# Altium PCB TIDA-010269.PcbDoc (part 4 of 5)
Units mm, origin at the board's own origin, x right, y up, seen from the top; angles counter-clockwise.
Board outline 87.61 x 53.51 mm, 8 copper layers (Top Layer, GND1, Signal 1, Power 1, Power 2, Signal 2, Layer 1, Bottom Layer), stack 1.645 mm thick; 482 components, 227 nets, 1562 pads, 953 vias.
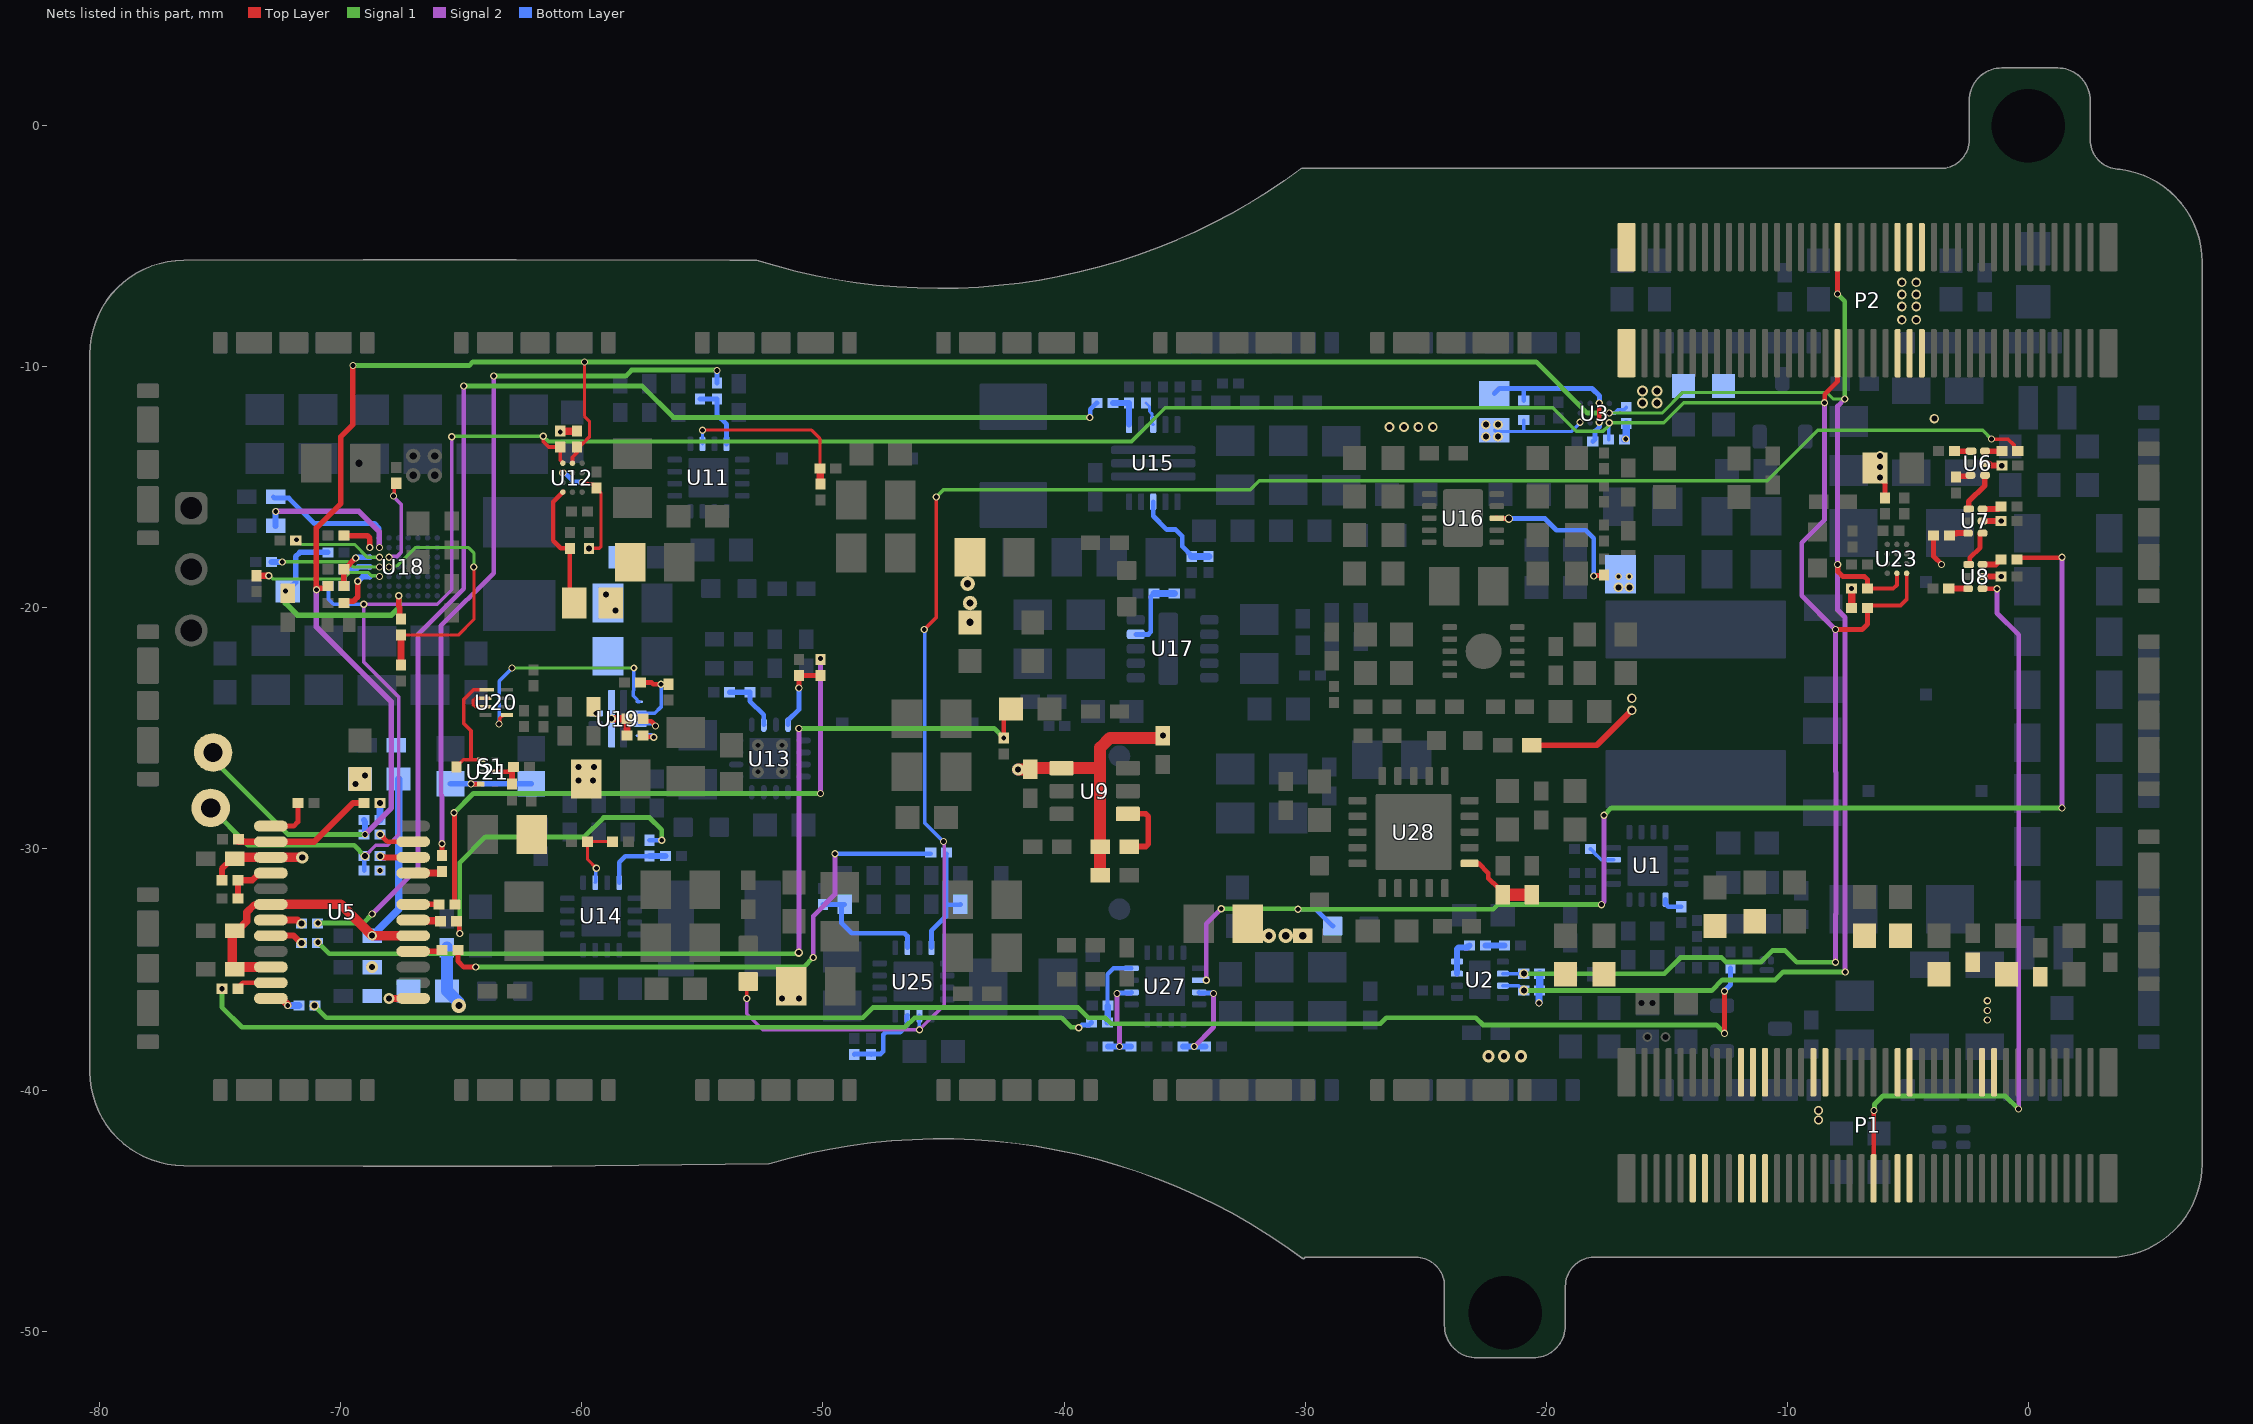
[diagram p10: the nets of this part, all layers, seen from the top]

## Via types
v1: diameter 0.6, hole 0.3, Top Layer to Bottom Layer, tented both sides, 264 vias
v2: diameter 0.4, hole 0.25, Top Layer to Bottom Layer, tented both sides, 251 vias
v3: diameter 0.3, hole 0.2, Top Layer to Bottom Layer, tented both sides, 153 vias
v4: diameter 0.3, hole 0.2, Top Layer to Bottom Layer, 95 vias
v5: diameter 0.5, hole 0.25, Top Layer to Bottom Layer, tented both sides, 67 vias
v6: diameter 0.5, hole 0.2, Top Layer to Bottom Layer, 44 vias
v7: diameter 0.35, hole 0.22, Top Layer to Bottom Layer, tented both sides, 34 vias
v8: diameter 0.45, hole 0.3, Top Layer to Bottom Layer, tented both sides, 8 vias
v9: diameter 0.3, hole 0.15, Top Layer to Bottom Layer, tented both sides, 8 vias
v10: diameter 0.5, hole 0.3, Top Layer to Bottom Layer, tented both sides, 7 vias
v11: diameter 0.35, hole 0.25, Top Layer to Bottom Layer, tented both sides, 5 vias
v12: diameter 0.38, hole 0.25, Top Layer to Bottom Layer, tented both sides, 3 vias
v13: diameter 0.4, hole 0.22, Top Layer to Bottom Layer, tented both sides, 3 vias
v14: diameter 0.4, hole 0.25, Top Layer to Bottom Layer, 3 vias
v15: diameter 0.35, hole 0.2, Top Layer to Bottom Layer, tented both sides, 2 vias
v16: diameter 0.7, hole 0.5, Top Layer to Bottom Layer, tented both sides, 1 vias
v17: diameter 0.32, hole 0.21, Top Layer to Bottom Layer, tented both sides, 1 vias
v18: diameter 0.6, hole 0.3, Top Layer to Bottom Layer, 1 vias
v19: diameter 0.45, hole 0.25, Top Layer to Bottom Layer, tented both sides, 1 vias
v20: diameter 0.36, hole 0.25, Top Layer to Bottom Layer, tented both sides, 1 vias
v21: diameter 0.5, hole 0.25, Top Layer to Bottom Layer, 1 vias

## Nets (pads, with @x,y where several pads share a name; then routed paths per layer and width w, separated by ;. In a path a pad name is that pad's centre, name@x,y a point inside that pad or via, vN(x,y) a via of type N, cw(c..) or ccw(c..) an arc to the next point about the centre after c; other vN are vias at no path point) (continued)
NetR16_2: R16.2 R138.2 U18.H5 | length 2
  Top Layer w0.23: R16.2@-69.87,-19.1 R138.2@-69.87,-18.4 -69.85,-18.4 v4(-69.383,-17.933)
  Bottom Layer w0.23: v4(-69.383,-17.933) -69.37,-17.9 U18.H5@-68.8,-17.9
NetR17_2: R17.2 U1.11 | length 1.2
  Bottom Layer w0.152: R17.2@-18.17,-30 -18.15,-30 -18.016,-30.134 -18.016,-30.154 -17.72,-30.45 U1.11@-17.2,-30.45
NetR18_2: R18.2 U1.5 | length 0.9
  Bottom Layer w0.2: U1.5@-15.05,-32.1 -15.05,-32.28 -14.93,-32.4 R18.2@-14.4,-32.4
NetR24_1: R24.1 U2.7 U2.8 | length 1.7
  Bottom Layer w0.152: R24.1@-23.292,-34 R24.1@-23.18,-34
  Bottom Layer w0.254: U2.7@-23.7,-35.175 U2.8@-23.7,-34.675 -23.7,-34.15 -23.633,-34.083 -23.263,-34.083 R24.1@-23.18,-34
NetR24_2: R24.2 R25.2 | length 0.8
  Bottom Layer w0.254: R24.2@-22.52,-34 R25.2@-21.73,-34
NetR37_1: R37.1 U5.1 | length 2
  Top Layer w0.2: U5.1@-72.9,-29.05 -71.95,-29.05 -71.78,-28.88 R37.1@-71.78,-28.1
NetR40_1: R40.1 R48.1 U5.2 | length 5.9
  Top Layer w0.254: R48.1@-74.24,-29.7 U5.2@-72.9,-29.7 -71.1,-29.7 -69.5,-28.1 R40.1@-69.03,-28.1
NetR41_1: R41.1 R49.1 U5.4 | length 2.2
  Top Layer w0.254: R49.1@-74.27,-32.05 R41.1@-74.27,-31.3 -73.675,-31.3 -73.375,-31 U5.4@-72.9,-31
NetR42_2: R42.2 U6.1 | length 0.7
  Top Layer w0.24: R42.2@-3.07,-13.5 U6.1@-2.375,-13.5
NetR43_2: R43.2 U6.3 | length 0.6
  Top Layer w0.22: R43.2@-3,-14.57 -2.965,-14.535 -2.435,-14.535 U6.3@-2.4,-14.5
NetR44_1: R44.1 U5.22 | length 1.4
  Top Layer w0.25: v7(-68.37,-30.3) -68.3,-30.3 -68.25,-30.35 U5.22@-67,-30.35
NetR45_1: R45.1 U5.23 | length 1.5
  Top Layer w0.2: v7(-68.37,-29.4) -68.07,-29.7 U5.23@-67,-29.7
NetR46_2: R46.2 U6.6 | length 0.7
  Top Layer w0.24: U6.6@-1.8,-13.5 R46.2@-1.1,-13.5
NetR47_2: R47.2 U5.12 | length 1.3
  Top Layer w0.3: U5.12@-72.9,-36.2 -72.463,-36.2 -72.2,-36.463 v4(-72.2,-36.5)
  Bottom Layer w0.3: v4(-72.2,-36.5) R47.2@-71.73,-36.5
NetR50_2: R50.2 U5.11 | length 1.5
  Top Layer w0.2: R50.2@-74.27,-35.8 -74.27,-35.75 -74.07,-35.55 U5.11@-72.9,-35.55
NetR51_2: R51.2 U7.3 | length 0.8
  Top Layer w0.24: R51.2@-3.27,-17 -3.18,-16.91 -2.98,-16.91 -2.97,-16.9 U7.3@-2.5,-16.9
NetR53_2: R53.2 U5.16 | length 1.2
  Top Layer w0.13: R53.2@-65.85,-34.25 R53.2@-65.8,-34.2
  Top Layer w0.23: U5.16@-67,-34.25 R53.2@-65.85,-34.25
NetR54_2: R54.2 U7.6 | length 0.8
  Top Layer w0.24: U7.6@-1.9,-15.9 -1.25,-15.9 -1.15,-15.8 R54.2@-1.13,-15.8
NetR55_2: R55.2 U5.8 | length 1.4
  Top Layer w0.25: U5.8@-72.9,-33.6 -71.955,-33.6 -71.655,-33.9 v2(-71.63,-33.9)
NetR56_2: R56.2 U5.7 | length 1.3
  Top Layer w0.3: U5.7@-72.9,-32.95 -71.807,-32.95 -71.657,-33.1 v2(-71.63,-33.1)
NetR57_2: R57.2 U5.18 | length 1.2
  Top Layer w0.25: U5.18@-67,-32.95 U5.18@-66.975,-32.975 ; R57.2@-65.885,-32.975 R57.2@-65.86,-33
  Top Layer w0.3: U5.18@-66.975,-32.975 R57.2@-65.885,-32.975
NetR58_2: R58.2 U5.19 | length 1.1
  Top Layer w0.23: U5.19@-67,-32.3 R58.2@-65.93,-32.3
NetR59_2: R59.2 U5.21 | length 1.2
  Top Layer w0.3: U5.21@-67,-31 R59.2@-65.8,-31
NetR60_2: R60.2 U8.3 | length 0.8
  Top Layer w0.24: R60.2@-3.3,-19.2 U8.3@-2.5,-19.2
NetR61_2: R61.2 U8.6 | length 0.9
  Top Layer w0.24: U8.6@-1.9,-18.2 -1.35,-18.2 -1.15,-18 R61.2@-1.13,-18
NetR63_1: R63.1 U9.4 | length 2.9
  Top Layer w0.23: U9.4@-37.35,-28.55 -36.611,-28.55 -36.5,-28.661 -36.5,-29.789 -36.611,-29.9 R63.1@-37.3,-29.9
NetR68_1: R68.1 R74.2 U11.6 | length 7.5
  Top Layer w0.13: v4(-55,-12.63) -50.47,-12.63 -50.13,-12.97 R68.1@-50.13,-14.225
  Top Layer w0.3: R68.1@-50.13,-14.225 -50.115,-14.24 -50.115,-14.855 R74.2@-50.1,-14.87
  Bottom Layer w0.13: U11.6@-55,-13.2 v4(-55,-12.63)
NetR75_1: R75.1 R189.1 U11.8 | length 2.7
  Bottom Layer w0.2: R75.1@-55.1,-11.33 R189.1@-54.4,-11.33 -54.4,-11.992 -54,-12.392 U11.8@-54,-13.2
NetR83_1: R83.1 R85.2 U14.6 | length 2.9
  Top Layer w0.127: v4(-59.4,-30.8) -59.77,-30.43 R85.2@-59.77,-29.7 R83.1@-58.73,-29.7
  Bottom Layer w0.127: U14.6@-59.45,-31.4 -59.425,-31.375 -59.425,-30.825 v4(-59.4,-30.8)
NetR84_1: R84.1 R87.2 U13.6 | length 2.4
  Bottom Layer w0.2: R84.1@-53.03,-23.5 -53.03,-23.87 -52.458,-24.442 -52.458,-24.842 U13.6@-52.45,-24.85
  Bottom Layer w0.22: R87.2@-53.87,-23.5 R84.1@-53.03,-23.5
NetR86_1: R86.1 R191.1 U14.8 | length 2.9
  Bottom Layer w0.2: U14.8@-58.45,-31.4 -58.45,-30.55 -58.2,-30.3 R191.1@-57.2,-30.3
  Bottom Layer w0.254: R191.1@-57.2,-30.3 R86.1@-56.53,-30.3
NetR88_1: R88.1 R190.1 U13.8 | length 3.1
  Top Layer w0.2: v4(-51,-23.33) R88.1@-51,-22.8 R190.1@-50.1,-22.8
  Bottom Layer w0.2: U13.8@-51.45,-24.85 -51.45,-24.67 -51,-24.22 v4(-51,-23.33)
NetR92_2: R92.2 R94.2 U15.11 | length 3.8
  Bottom Layer w0.2: U15.11@-36.3,-15.6 -36.3,-16.19 -35.735,-16.755 -35.369,-16.755 -35.099,-17.024 -35.099,-17.451 -34.7,-17.85 R94.2@-34.7,-17.87
  Bottom Layer w0.3: R94.2@-34.7,-17.87 R92.2@-34,-17.87
NetR96_2: R96.2 R192.2 U15.1 | length 1.6
  Bottom Layer w0.254: R192.2@-37.97,-11.5 R96.2@-37.3,-11.5 U15.1@-37.3,-12.4
NetR97_2: R97.2 U15.3 | length 1
  Bottom Layer w0.127: R97.2@-36.6,-11.5 -36.454,-11.647 -36.454,-11.852 -36.357,-11.948 -36.357,-12.343 U15.3@-36.3,-12.4
NetR103_2: R103.2 U16.8 | length 6.4
  Top Layer w0.2: v3(-18.025,-18.682) -18.006,-18.663 -17.633,-18.663 R103.2@-17.6,-18.63
  Top Layer w0.22: U16.8@-22.05,-16.28 -22.04,-16.29 -21.56,-16.29 v11(-21.55,-16.3)
  Bottom Layer w0.2: v11(-21.55,-16.3) -20.05,-16.3 -19.573,-16.777 -18.365,-16.777 -18.025,-17.117 v3(-18.025,-18.682)
NetR108_1: R108.1 R110.2 U17.4 | length 3.2
  Bottom Layer w0.13: R108.1@-36.4,-19.53 R108.1@-36.27,-19.4
  Bottom Layer w0.2: U17.4@-37.025,-21.1 -36.5,-21.1 -36.4,-21 R108.1@-36.4,-19.53
  Bottom Layer w0.3: R108.1@-36.27,-19.4 R110.2@-35.43,-19.4
NetR121_1: R121.1 R127.1 U19.2 | length 3.2
  Top Layer w0.2: R121.1@-57.57,-23.1 -57.1,-23.1 -57.03,-23.17 v4(-56.715,-23.17) R127.1@-56.4,-23.17
  Bottom Layer w0.15: U19.2@-57.619,-24.375 -56.975,-24.375 -56.715,-24.115 v4(-56.715,-23.17)
NetR122_2: R122.2 U19.4 | length 1.1
  Top Layer w0.2: R122.2@-57.47,-25.3 -57.42,-25.35 -57.038,-25.35 v3(-57.019,-25.369)
  Bottom Layer w0.2: U19.4@-57.619,-25.3 -57.116,-25.3 -57.046,-25.369 v3(-57.019,-25.369)
NetR123_1: R123.1 U20.1 U21.1 | length 4.9
  Top Layer w0.15: R123.1@-65.2,-26.6 -65.2,-26.58 -64.92,-26.3 -64.6,-26.3 ; U21.1@-64.175,-26.3 -64.6,-26.3 ; U20.1@-63.95,-23.4 -64.5,-23.4 -64.9,-23.8 -64.9,-24.8 -64.6,-25.1 -64.6,-26.3
NetR124_2: R124.2 R132.2 U21.5 | length 1.6
  Top Layer w0.2: U21.5@-63.6,-26.8 -63.05,-26.8 -62.85,-26.6 R132.2@-62.83,-26.6
  Top Layer w0.23: R124.2@-62.9,-27.3 -62.9,-26.67 R132.2@-62.83,-26.6
NetR125_2: R125.2 U19.3 | length 1.4
  Top Layer w0.2: R125.2@-57.47,-24.6 -57.37,-24.7 -57.127,-24.7 -56.927,-24.9 v3(-56.946,-24.9)
  Bottom Layer w0.13: U19.3@-57.619,-24.825 -57.021,-24.825 v3(-56.946,-24.9)
NetR126_1: R126.1 U18.F5 | length 3.6
  Top Layer w0.15: v3(-67.811,-15.36) -67.782,-15.331 -67.782,-14.912 R126.1@-67.7,-14.83
  Signal 2 w0.15: v4(-68,-17.9) -67.971,-17.871 -67.671,-17.871 -67.5,-17.7 -67.5,-15.7 -67.811,-15.389 v3(-67.811,-15.36)
NetR128_1: R128.1 R130.1 U18.F4 | length 11.3
  Top Layer w0.13: R128.1@-67.5,-21.13 -65.13,-21.13 -64.483,-20.483 v4(-64.483,-18.3)
  Top Layer w0.3: R130.1@-67.5,-22.4 R128.1@-67.5,-21.13
  Signal 2 w0.13: v4(-68,-18.3) v4@-67.967,-18.267
  Signal 1 w0.13: v4(-68,-18.3) -67.967,-18.267 -67.684,-18.267 -66.916,-17.5 -64.7,-17.5 -64.483,-17.717 v4(-64.483,-18.3)
NetR129_2: R129.2 U19.9
  other v4: -59.419,-24.375
NetR134_1: R134.1 U18.G7 | length 5.3
  Bottom Layer w0.2: R134.1@-72.8,-15.4 -72.753,-15.447 -72.153,-15.447 -71.1,-16.5 -68.6,-16.5 -68.406,-16.694 -68.406,-17.094 U18.G7@-68.4,-17.1
NetR135_1: R135.1 U18.G6 | length 5.9
  Signal 2 w0.23: v4(-72.7,-16) -69.25,-16 -68.4,-16.85 v4(-68.4,-17.5)
  Bottom Layer w0.25: R135.1@-72.7,-16.6 v4(-72.7,-16)
NetR139_2: R139.2 R193.2 U18.H4 | length 1.8
  Bottom Layer w0.23: R193.2@-69.87,-19.1 R139.2@-69.87,-18.4 -69.375,-18.4 -69.275,-18.3 U18.H4@-68.8,-18.3
NetR140_2: R140.2 U18.G3 | length 5.3
  Top Layer w0.254: R140.2@-73.5,-18.67 v3(-72.99,-18.67)
  Signal 2 w0.13: v3(-72.99,-18.67) v3@-72.953,-18.67 ; v4@-68.433,-18.667 v4(-68.4,-18.7)
  Signal 1 w0.13: v3@-72.953,-18.67 -72.823,-18.8 -69.9,-18.8 -69.63,-18.53 -68.87,-18.53 -68.733,-18.667 v4@-68.433,-18.667
NetR141_2: R141.2 U18.G4 | length 4.6
  Signal 1 w0.13: v4(-72.43,-18.1) -72.415,-18.085 -69.715,-18.085 -69.5,-18.3 v4(-68.4,-18.3)
  Bottom Layer w0.254: R141.2@-72.87,-18.1 v4(-72.43,-18.1)
NetR142_2: R142.2 U18.H6 | length 1.5
  Top Layer w0.23: R142.2@-69.87,-17 -68.903,-17 -68.8,-17.103 v4(-68.8,-17.5)
NetR143_2: R143.2 U18.H3 | length 1.9
  Top Layer w0.23: R143.2@-69.87,-19.8 -69.796,-19.726 -69.476,-19.726 -69.3,-19.55 v4(-69.3,-18.9)
  Bottom Layer w0.23: v4(-69.3,-18.9) -69.281,-18.9 -69.081,-18.7 U18.H3@-68.8,-18.7
NetR144_2: R144.2 U18.G5 | length 3.7
  Signal 1 w0.13: v4(-71.836,-17.173) -71.644,-17.365 -69.435,-17.365 -68.9,-17.9 v4(-68.4,-17.9)
NetR161_2: R161.2 R162.2 U25.15 | length 3.5
  Bottom Layer w0.2: R161.2@-48.7,-38.53 -48.7,-38.5 R162.2@-48,-38.5 ; R162.2@-48,-38.53 -47.97,-38.5 -47.603,-38.5 -47.5,-38.397 -47.5,-37.702 -47.397,-37.6 -46.8,-37.6 -46.641,-37.441 ; -46.6,-37.4 -46.52,-37.32 -46.52,-36.92 U25.15@-46.5,-36.9
NetR165_1: R165.1 R168.2 U25.6 | length 5.2
  Bottom Layer w0.16: R165.1@-49.225,-32.425 R165.1@-49.1,-32.3
  Bottom Layer w0.2: R168.2@-50,-32.3 R165.1@-49.1,-32.3 ; R165.1@-49.225,-32.425 -49.225,-33.075 -48.8,-33.5 -46.617,-33.5 -46.5,-33.617 U25.6@-46.5,-34.1
NetR169_1: R169.1 R186.1 U25.8 | length 4.8
  Bottom Layer w0.2: U25.8@-45.5,-34.1 -45.5,-33.4 -44.9,-32.8 -44.9,-32.315 ; R186.1@-44.87,-30.2 -44.9,-30.23 -44.9,-32.315 ; R169.1@-44.3,-32.3 -44.315,-32.315 -44.9,-32.315
NetR173_2: R173.2 R174.2 U27.15 | length 4.1
  Signal 2 w0.2: v4(-34.6,-38.2) -33.8,-37.4 v4(-33.8,-36)
  Bottom Layer w0.2: U27.15@-34.4,-35.95 -34.38,-35.97 -33.857,-35.97 v4(-33.8,-36)
  Bottom Layer w0.254: R173.2@-35.07,-38.2 v4(-34.6,-38.2) R174.2@-34.13,-38.2
NetR177_1: R177.1 R180.2 U27.6 | length 3.8
  Signal 2 w0.2: v4(-37.8,-36) -37.8,-37.212 -37.7,-37.312 v4(-37.7,-38.2)
  Bottom Layer w0.2: v4(-37.8,-36) -37.781,-35.981 -37.581,-35.981 -37.57,-35.97 -37.22,-35.97 U27.6@-37.2,-35.95
  Bottom Layer w0.254: R177.1@-38.17,-38.2 v4(-37.7,-38.2) R180.2@-37.23,-38.2
NetR179_1: R179.1 R182.2 U28.16 | length 3.3
  Top Layer w0.2: U28.16@-23.175,-30.6 -22.8,-30.6 -22.4,-31 -22.4,-31.224 -22.224,-31.4 -22.2,-31.4 -21.8,-31.8 R179.1@-21.8,-31.9
  Top Layer w0.5: R179.1@-21.8,-31.9 R182.2@-20.6,-31.9
NetR181_1: R181.1 R187.1 U27.8 | length 3.1
  Bottom Layer w0.18: R181.1@-38.17,-36.5 -38.185,-36.515 -38.2,-36.5 -38.2,-35.2 -37.95,-34.95 U27.8@-37.2,-34.95
  Bottom Layer w0.254: R187.1@-38.2,-37.2 -38.185,-37.185 R181.1@-38.185,-36.515
NetS1_2: S1.2 S1.4 U21.3 | length 3.7
  Top Layer w0.2: v4(-64.6,-27.3) U21.3@-64.2,-27.3
  Bottom Layer w0.23: S1.4@-65.45,-27.3 v4(-64.6,-27.3) S1.2@-62.1,-27.3
NetU6_4: U6.4 U7.1 | length 1.7
  Top Layer w0.23: U7.1@-2.475,-15.9 -2.475,-15.593 -1.8,-14.917 U6.4@-1.8,-14.5
NetU7_4: U7.4 U8.1 | length 1.6
  Top Layer w0.2: U8.1@-2.475,-18.2 -2.428,-18.153 -2.428,-17.928 -2,-17.5 -2,-16.95 -1.95,-16.9 U7.4@-1.9,-16.9
NetU19_1: U19.1 U20.5 | length 9.8
  Top Layer w0.14: v4(-63.435,-24.818) -63.404,-24.787 -63.404,-24.584 -63.27,-24.45 U20.5@-63.1,-24.45
  Signal 1 w0.14: v3(-62.895,-22.495) v9(-57.842,-22.495)
  Bottom Layer w0.14: v4(-63.435,-24.818) -63.435,-23.035 v3(-62.895,-22.495) ; v9(-57.842,-22.495) -57.842,-23.421 -57.87,-23.45 -57.87,-23.649 -57.699,-23.82 -57.699,-23.88 -57.679,-23.9 U19.1@-57.619,-23.9
NetU20_2: U20.2 U20.3 | length 1.2
  Top Layer w0.14: U20.3@-64,-24.1 -64.412,-24.1 -64.5,-24.012 -64.5,-23.838 -64.412,-23.75 U20.2@-64,-23.75
PHV: C13.1 L4.2 P2.79 P2.80
  other v8: -16,-11.5 -15.4,-11.5 -16,-11 -15.4,-11
"Power Good": P1.39 U8.4 | length 32
  Top Layer w0.2: P1.39@-6.421,-43.664 -6.41,-43.654 -6.41,-40.86 v3(-6.4,-40.85) ; U8.4@-1.9,-19.2 -1.895,-19.205 -1.305,-19.205 v3(-1.3,-19.21)
  Signal 2 w0.2: v3(-1.3,-19.21) -1.3,-20.217 -0.4,-21.117 v3@-0.4,-40.793
  Signal 1 w0.2: v3(-6.4,-40.85) -6.381,-40.831 -6.381,-40.599 -6.031,-40.249 -0.949,-40.249 v3(-0.406,-40.793)
RX_PG_1V2: D14.2 R61.1 U27.14 | length 56
  Top Layer w0.2: R61.1@-0.47,-18 -0.389,-17.919 1.381,-17.919 v4(1.4,-17.9)
  Signal 2 w0.2: v4(-34.1,-35.45) -34.1,-33.101 v3(-33.481,-32.482) ; v3(-17.704,-32.311) -17.704,-32.284 -17.6,-32.18 v3(-17.6,-28.6) ; v3(1.4,-28.3) v4(1.4,-17.9)
  Signal 1 w0.2: v3(-33.481,-32.482) v3@-30.3,-32.482 ; v3(-30.3,-32.5) -22.2,-32.5 -22.011,-32.311 v3(-17.704,-32.311) ; v3(-17.6,-28.6) -17.3,-28.3 v3(1.4,-28.3)
  Bottom Layer w0.2: v3(-30.3,-32.5) -29.55,-32.5 D14.2@-28.85,-33.2
RX_PG_1V8: D7.2 R46.1 U25.14 | length 78.9
  Top Layer w0.15: v4(-53.163,-36.2) -53.163,-35.563 D7.2@-53.1,-35.5 ; v3(-45.8,-20.9) -45.3,-20.4 v3(-45.3,-15.4) ; v3(-1.525,-13) -0.842,-13 -0.595,-13.247 -0.595,-13.365 -0.46,-13.5 R46.1@-0.44,-13.5
  Signal 2 w0.15: v4(-53.163,-36.2) -53.163,-36.837 -52.5,-37.5 -52.495,-37.495 -46.005,-37.495 v4(-46,-37.5) -44.975,-36.475 -44.975,-29.715 v3(-45,-29.69)
  Signal 1 w0.15: v3(-45.3,-15.4) -45,-15.1 -32.281,-15.1 -31.906,-14.725 -10.825,-14.725 -8.734,-12.634 -1.891,-12.634 v3(-1.525,-13)
  Bottom Layer w0.15: v4(-46,-37.5) U25.14@-46,-36.9 ; v3(-45.8,-20.9) -45.775,-20.925 -45.775,-28.925 -45.01,-29.69 v3(-45,-29.69)
SCL: P2.45 R27.2 R32.1 R38.1 R44.2 R73.1 R148.1 R193.1 SCL.1 U2.2 U3.A1 U12.A1 U23.A1 | length 139
  Top Layer w0.152: v3(-61.603,-12.881) -61.6,-12.884 -61.6,-13.1 -61.37,-13.33 R73.1@-60.9,-13.33 -60.9,-13.869 -60.79,-13.979 U12.A1@-60.79,-14 ; R148.1@-6.67,-20 -6.67,-19.9 -5.3,-19.9 -5.05,-19.65 U23.A1@-5.05,-18.565
  Top Layer w0.2: v4(-8.459,-11.495) -8.445,-11.482 -8.445,-11.145 -7.921,-10.621 P2.45@-7.921,-9.438 ; v4(-8,-20.9) -6.9,-20.9 -6.67,-20.67 R148.1@-6.67,-20
  Signal 2 w0.15: v20(-69,-30.3) -68.55,-29.85 -68.05,-29.85 -67.6,-29.4 -67.6,-23.7 -69.05,-22.25 v3(-69.05,-19.85) -66,-19.85 -65.4,-19.25 v4(-65.4,-12.9)
  Signal 2 w0.2: v4(-8.459,-11.495) -8.459,-16.359 -9.4,-17.3 -9.4,-19.5 v4(-8,-20.9) ; v4@-8.033,-20.933 -8.014,-20.933 -8,-20.946 -8,-26.794 -7.975,-26.819 -7.975,-32.686 -8,-32.711 v3(-8,-34.7)
  Signal 1 w0.15: v4(-65.4,-12.9) -65.381,-12.881 v3(-61.603,-12.881) -61.384,-13.1 -37.2,-13.1 -35.8,-11.7 -19.73,-11.7 -18.755,-12.675 -17.645,-12.675 v3@-17.41,-12.44 ; v3(-17.381,-12.319) -15.119,-12.319 -14.295,-11.495 v4(-8.459,-11.495)
  Signal 1 w0.2: SCL.1@-75.4,-28.3 -73.85,-29.85 -69.45,-29.85 v20(-69,-30.3) ; v2(-20.93,-35.175) -15.098,-35.175 -14.428,-34.505 -12.716,-34.505 -12.526,-34.695 -11.1,-34.695 -10.62,-34.215 -10.085,-34.215 -9.6,-34.7 v3(-8,-34.7)
  Bottom Layer w0.15: R193.1@-70.51,-19.1 -70.51,-19.64 -70.3,-19.85 v3(-69.05,-19.85)
  Bottom Layer w0.152: U2.2@-21.8,-35.175 v2(-20.93,-35.175) ; R32.1@-17.411,-13.019 -17.411,-12.37 -17.381,-12.34 v3(-17.381,-12.319)
  Bottom Layer w0.2: R38.1@-69.03,-30.9 -69.03,-30.33 v20(-69,-30.3)
SDA: P2.46 R16.1 R26.2 R33.1 R39.1 R45.2 R72.1 R149.1 SDA.1 U2.3 U3.A2 U12.A2 U23.A2 | length 149.1
  Top Layer w0.13: R72.1@-60.2,-13.445 -60.143,-13.387 -59.69,-12.935 ; R72.1@-60.2,-13.33 -60.2,-13.31 -60.055,-13.165 -59.951,-13.165 -59.69,-12.904 -59.69,-12.253 -59.897,-12.047 v3(-59.897,-9.8)
  Top Layer w0.152: U12.A2@-60.39,-14 -60.39,-13.75 -60.2,-13.56 R72.1@-60.2,-13.445 ; R149.1@-6.67,-19.2 -5.6,-19.2 -5.45,-19.05 U23.A2@-5.45,-18.565
  Top Layer w0.2: v4(-7.921,-6.979) P2.46@-7.921,-5.038 ; v4(-7.91,-18.2) -7.891,-18.219 -7.891,-18.509 -7.7,-18.7 -6.8,-18.7 -6.67,-18.83 R149.1@-6.67,-19.2
  Top Layer w0.23: R16.1@-70.53,-19.1 -70.625,-19.195 -70.936,-19.195 -70.991,-19.25 v4(-71.01,-19.25) -71.01,-16.682 -70,-15.672 -70,-12.899 -69.5,-12.399 v3(-69.5,-9.95)
  Signal 2 w0.2: v3(-7.615,-11.333) -7.91,-11.628 v4(-7.91,-18.2) -7.91,-20.09 -7.6,-20.4 -7.6,-35.099 v3(-7.597,-35.101)
  Signal 2 w0.23: v4(-71.01,-19.25) -71.01,-20.79 -67.9,-23.9 -67.9,-28.3 v4(-69,-29.4)
  Signal 1 w0.13: v4@-69.03,-29.4 v4(-69,-29.4) ; v3(-17.381,-11.919) -15.186,-11.919 -14.331,-11.063 -8.375,-11.063 -8.105,-11.333 v3(-7.615,-11.333)
  Signal 1 w0.2: SDA.1@-75.3,-26 -75.3,-26.3 -72.2,-29.4 v4@-69.03,-29.4 ; v3(-69.5,-9.95) -64.678,-9.95 -64.528,-9.8 v3(-59.897,-9.8) -20.416,-9.8 -18.297,-11.919 v3(-17.381,-11.919) ; v2(-20.93,-35.875) -13.141,-35.875 -12.701,-35.435 -10.501,-35.435 -10.166,-35.1 -9.834,-35.1 -9.833,-35.101 v3(-7.597,-35.101) ; v4@-7.91,-6.99 v4(-7.921,-6.979) -7.615,-7.285 v3(-7.615,-11.333)
  Bottom Layer w0.152: U2.3@-21.8,-35.675 -21.15,-35.675 -20.95,-35.875 v2(-20.93,-35.875) ; v3(-17.381,-11.919) -17.158,-11.919 -17.028,-11.788 -16.781,-11.788 R33.1@-16.681,-11.689
  Bottom Layer w0.25: R39.1@-69.03,-28.8 -69,-28.9 v4(-69,-29.4)
SYNC_1V2_RX: R50.1 R187.2 | length 37.6
  Signal 1 w0.2: v13(-74.93,-35.8) -74.93,-36.57 -74.1,-37.4 -46.6,-37.4 -46.2,-37 -40.1,-37 -39.705,-37.395 -39.409,-37.395 v3(-39.39,-37.414)
  Bottom Layer w0.2: v3(-39.39,-37.414) -39.363,-37.414 -39.259,-37.31 -38.97,-37.31 R187.2@-38.86,-37.2
SYNC_1V8_FX3: R57.1 R191.2 | length 13.8
  Top Layer w0.2: R57.1@-65.2,-33 -65.197,-33 -65.087,-33.11 -65.087,-33.491 v3(-65.068,-33.51)
  Signal 1 w0.2: v3(-65.068,-33.51) -65.068,-30.568 -64,-29.5 -59.9,-29.5 -59.1,-28.7 -57.196,-28.7 -56.69,-29.206 v3(-56.69,-29.64)
  Bottom Layer w0.2: R191.2@-57.2,-29.64 v3(-56.69,-29.64)
SYNC_1V8_RX: R53.1 R186.2 | length 24.1
  Top Layer w0.2: R53.1@-65.14,-34.2 -65.14,-34.66 -64.9,-34.9 v3(-64.4,-34.9)
  Signal 2 w0.2: v3(-50.4,-34.5) -50.4,-32.786 -49.5,-31.886 v3(-49.5,-30.2)
  Signal 1 w0.2: v3(-64.4,-34.9) -50.8,-34.9 v3(-50.4,-34.5)
  Bottom Layer w0.2: v3(-49.5,-30.2) R186.2@-45.53,-30.2
SYNC_5V_TX: R56.1 R192.1 | length 53.1
  Signal 2 w0.2: v3(-68.7,-32.7) -66.8,-30.8 -66.8,-21.11 -64.9,-19.21 v3(-64.9,-10.8)
  Signal 1 w0.2: v7(-70.949,-33.076) -69.076,-33.076 v3(-68.7,-32.7) ; v3(-64.9,-10.8) -57.5,-10.8 -56.2,-12.1 v3(-38.933,-12.1)
  Bottom Layer w0.2: v3(-38.933,-12.1) -38.914,-12.081 -38.914,-11.764 -38.65,-11.5 R192.1@-38.63,-11.5
SYNC_-5V_TX: C124.2 R55.1 R111.2 | length 39.5
  Top Layer w0.2: v3(-42.5,-25.4) -42.5,-24.5 C124.2@-42.2,-24.2
  Signal 2 w0.2: v7(-51,-34.3) v3(-51,-25)
  Signal 1 w0.2: v7(-70.949,-33.876) -70.475,-34.35 -51.05,-34.35 v7(-51,-34.3) ; v3(-51,-25) -42.9,-25 v3(-42.5,-25.4)
SYNC_FPGA_1V: R58.1 R190.2 | length 24.9
  Top Layer w0.2: v3(-65.3,-28.5) -65.285,-28.515 -65.285,-32.285 R58.1@-65.27,-32.3
  Signal 2 w0.2: v3(-50.1,-27.7) v3(-50.1,-22.1)
  Signal 1 w0.2: v3(-65.3,-28.5) -64.5,-27.7 v3(-50.1,-27.7)
SYNC_FPGA_2V5: R59.1 R189.2 | length 30.7
  Top Layer w0.2: R59.1@-65.8,-30.27 v3(-65.8,-29.781)
  Signal 2 w0.2: v3(-65.8,-29.781) -65.8,-27.794 -65.85,-27.744 -65.85,-20.75 -63.656,-18.556 v3(-63.656,-10.387)
  Signal 1 w0.2: v3(-63.656,-10.387) -58.187,-10.387 -57.94,-10.14 -54.41,-10.14 v3(-54.4,-10.15)
  Bottom Layer w0.2: R189.2@-54.4,-10.67 v3(-54.4,-10.15)
SYNC_HV_TX: R12.1 R47.1 | length 62.4
  Top Layer w0.2: v3(-12.6,-37.65) v3(-12.6,-35.9)
  Signal 1 w0.2: v2(-71.1,-36.5) -70.6,-37 -48.343,-37 -47.918,-36.575 -39.425,-36.575 -39,-37 -38.3,-37 -38.05,-37.25 -26.88,-37.25 -26.63,-37 -22.922,-37 -22.622,-37.3 -12.95,-37.3 v3(-12.6,-37.65)
  Bottom Layer w0.2: v3(-12.6,-35.9) -12.6,-35.873 -12.35,-35.623 R12.1@-12.35,-34.93
USB_5V: P2.31 P2.32 P2.33 P2.34 P2.35 P2.36 R116.1 R146.2 | length 1.5
  Top Layer w0.2: R116.1@-6.36,-14.2 -6.46,-14.2 -6.46,-14.325 -5.95,-14.835 R146.2@-5.95,-15.435
  other v2: -6.15,-14.6 -6.15,-14.15 -6.15,-13.7 -3.9,-12.15 -5.25,-8.05 -4.65,-8.05 -5.25,-7.5 -4.65,-7.5 -5.25,-7 -4.65,-7 -5.25,-6.5 -4.65,-6.5
VBUS: C16.1 C34.1 C53.1 C54.1 C55.1 C61.1 C131.1 C132.1 C133.1 pad.8@-43.9,-20.6 pad.9@-43.9,-19.8 pad.10@-44,-19 R9.2 R28.1 R30.2 R51.1 R62.2 R63.2 R66.1 R70.2 R91.1 R105.1 R122.1 R125.1 R163.1 R164.2 R175.1 R176.2 U3.B1 U3.B3 U6.5 U7.5 U8.5 U9.1 U12.B1 U12.C3 U19.6 | length 33.1
  Top Layer w0.127: U12.C3@-59.99,-14.8 -59.97,-14.82 -59.763,-14.82 -59.719,-14.864 -59.547,-14.864 -59.4,-15.01 C61.1@-59.4,-15.03
  Top Layer w0.13: v2(-59.7,-17.53) -59.282,-17.53 -59.2,-17.448 -59.2,-15.25 -59.4,-15.05 C61.1@-59.4,-15.03
  Top Layer w0.2: v3(-17.8,-12.3) v3(-17.8,-11.5) ; R51.1@-3.93,-17 -3.93,-17.87 v3(-3.6,-18.2)
  Top Layer w0.24: R164.2@-20.6,-25.7 -17.9,-25.7 v2(-16.45,-24.25) ; U8.5@-1.9,-18.7 v7(-1.13,-18.7) ; U7.5@-1.9,-16.4 v7(-1.13,-16.4) ; U6.5@-1.8,-14 -1.77,-14.03 -1.597,-14.03 -1.527,-14.1 v7(-1.1,-14.1)
  Top Layer w0.3: v7(-58.769,-24.6) R125.1@-58.13,-24.6 R122.1@-58.13,-25.3 ; C16.1@-41.4,-26.7 C16.1@-41.35,-26.65 ; -38.508,-26.65 -38.5,-26.658
  Top Layer w0.5: v5(-41.9,-26.7) C16.1@-41.4,-26.7 ; C16.1@-41.35,-26.65 U9.1@-40.1,-26.65 -38.508,-26.65 ; R62.2@-38.5,-31.1 R63.2@-38.5,-29.9 -38.5,-26.658 -38.5,-25.8 -38.1,-25.4 R9.2@-35.9,-25.4
  Signal 2 w0.2: pad.8@-43.9,-20.6 pad.8@-43.872,-20.572
  Signal 2 w0.24: v7(-1.13,-16.4) v7@-1.115,-16.385 ; v7@-1.115,-14.115 v7(-1.1,-14.1)
  Bottom Layer w0.2: v4(-60.79,-14.4) -60.771,-14.419 -60.686,-14.419 -60.324,-14.781 -60.019,-14.781 v4(-60,-14.8) ; R28.1@-22.151,-11.109 -21.943,-10.9 -20.912,-10.9 ; R30.2@-20.93,-11.4 -20.93,-10.918 -20.912,-10.9 ; C34.1@-18.07,-13.1 -17.97,-13 -17.97,-12.67 -17.787,-12.487 -17.787,-12.324 U3.B1@-17.781,-12.319 ; U3.B3@-17.781,-11.519 -17.787,-11.513 -17.787,-11.213 -18.1,-10.9 -20.912,-10.9
  other v1: -31.5,-33.6 -30.8,-33.6 -30.1,-33.6
  other v2: -35.9,-25.3 -16.45,-23.75 -26.5,-12.5 -25.9,-12.5 -25.3,-12.5 -24.7,-12.5
  other v5: -51.7,-36.2 -51,-36.2 -58.6,-20.1 -59,-19.45
VBUS_HV: R2.1 R28.2 R31.2 U3.D1 | length 4.3
  Signal 2 w0.13: v3(-18.6,-12.3) v3@-18.567,-12.333
  Bottom Layer w0.127: -20.93,-12.677 R31.2@-20.93,-12.2
  Bottom Layer w0.13: R28.2@-22.151,-12.629 -22.103,-12.677 -20.93,-12.677 -18.94,-12.677 U3.D1@-18.581,-12.319
  other v2: -17,-19.15 -16.55,-19.15 -22.5,-12.9 -22,-12.9 -22.5,-12.4 -22,-12.4
  other v9: -17,-18.7 -16.55,-18.7
VCC_AUX_1V8: C50.1 C86.1 L9.1 L15.2 P1.20 P1.22 R26.1 R27.1 R32.2 R33.2 R72.2 R73.2 R148.2 R149.2 | length 6.1
  Top Layer w0.3: v3(-60.9,-12.7) -60.87,-12.67 R72.2@-60.2,-12.67 ; R148.2@-7.33,-20 v3(-7.33,-19.2)
  Bottom Layer w0.3: v3(-20.3,-36.385) -20.3,-35.905 R26.1@-20.27,-35.875 R27.1@-20.27,-35.175 ; R32.2@-16.741,-13.019 -16.681,-12.959 R33.2@-16.681,-12.349
  Bottom Layer w0.5: C50.1@-65.6,-34.1 L9.1@-65.6,-35.9 -65.575,-35.9 -65.119,-36.356 -65.119,-36.481 v1(-65.1,-36.5)
  other v3: -1.7,-37.1 -1.7,-36.7 -1.7,-36.3 -16.7,-13
VCC_INT_1V: C87.1 L13.2 P1.33 P1.34 P1.35 P1.36
VCCO_2V5: C47.1 C57.1 L8.1 L11.2 P1.48 P1.50
  other v5: -22.4,-38.6 -21.75,-38.6 -21.05,-38.6 -69.4,-27.3 -69,-26.95
  other v12: -8.7,-41.25 -8.7,-40.85
VDD: C42.1 C43.1 C51.1 L9.2 R38.2 R39.2 R40.2 R41.2 U5.3 U5.13 | length 5.7
  Top Layer w0.254: R41.2@-74.93,-31.3 -74.93,-30.83 -74.5,-30.4 C42.1@-74.4,-30.4
  Top Layer w0.3: v19(-68,-36.2) U5.13@-67,-36.2
  Top Layer w0.4: C42.1@-74.4,-30.4 -74.35,-30.35 U5.3@-72.9,-30.35 v5(-71.6,-30.35)
  Signal 2 w0.3: v5@-68.792,-34.9 v5@-68.792,-34.862
  Bottom Layer w0.3: v2@-68.4,-28.1 -68.37,-28.13 R39.2@-68.37,-28.8
  other v2: -68.37,-28.1
  other v4: -68.37,-30.9
  other v5: -68.7,-34.9
VDD_CLK_2.5V: C39.1 C40.1 C41.1 C52.1 L8.2 U5.6 U5.10 U5.17 | length 18.6
  Top Layer w0.3: C39.1@-74.5,-34.85 -74.45,-34.9 C39.1@-74.4,-34.9 ; C40.1@-74.4,-33.4 -74.3,-33.4 -73.9,-33 -73.9,-32.624 -73.604,-32.329 -72.929,-32.329 U5.6@-72.9,-32.3
  Top Layer w0.4: C39.1@-74.5,-34.85 C40.1@-74.5,-33.5 ; C39.1@-74.4,-34.9 U5.10@-72.9,-34.9 ; U5.6@-72.9,-32.3 -70,-32.3 v2(-68.7,-33.6) U5.17@-67,-33.6
  Bottom Layer w0.3: v2(-68.7,-33.6) -68.6,-33.6 -68.45,-33.45 -68.45,-33.35 -67.6,-32.5 L8.2@-67.6,-27.1
VDD_FPGA: R66.2 R67.1 R71.2 R81.1 R82.1 U12.D1 | length 5.3
  Top Layer w0.152: R66.2@-60.5,-19.62 R66.2@-60.32,-19.8
  Top Layer w0.2: U12.D1@-60.79,-15.2 -61.19,-15.6 -61.19,-17.21 -60.87,-17.53 R71.2@-60.5,-17.53 R66.2@-60.5,-19.62
  other v5: -60.132,-27.158 -59.532,-27.158 -60.141,-26.593 -59.491,-26.6
VDDM_LV5: C117.1 L18.2 P1.67 P1.69
VDDP_LV5: C107.1 L17.2 P1.57 P1.58 P1.59 P1.60 P1.61 P1.62
VREG: C144.1 R128.2 R133.2 R136.2 U18.E1 | length 10.1
  Top Layer w0.23: v4(-67.6,-19.5) -67.6,-19.941 -67.55,-19.991 -67.55,-20.42 R128.2@-67.5,-20.47
  Signal 1 w0.23: v4@-72.3,-19.319 -72.3,-19.8 -71.8,-20.3 -67.9,-20.3 -67.6,-20 v4(-67.6,-19.5)
  Bottom Layer w0.23: v4(-72.3,-19.3) -72.233,-19.3 -71.873,-18.94 -71.873,-17.873 -71.7,-17.7 R136.2@-70.55,-17.7
pads on no net: D11.1S D11.2S D12.1S D12.2S P1.1 P1.2 P1.3 P1.4 P1.5 P1.6 P1.7 P1.8 P1.11 P1.12 P1.13 P1.14 P1.15 P1.16 P1.25 P1.29 P1.30 P1.75 P1.76 P1.77 P1.78 P2.1 P2.2 P2.5 P2.6 P2.9 P2.10 P2.13 P2.14 P2.15 P2.16 P2.19 P2.20 P2.21 P2.22 P2.25 P2.26 P2.27 P2.28 P2.37 P2.38 P2.43 P2.65 P2.66 P2.67 P2.68 P2.75 P2.76 P2.77 P2.78 Q3.1@-11.05,-34.625 Q3.2@-10.65,-34.625 U1.12 U1.15 U3.A3 U3.B2 U3.C2 U5.15 U5.24 U11.17@-54.75,-14.6 U12.A3 U12.B2 U12.C2 U14.17@-59.2,-32.8 U15.6@-35.1,-13.45 U15.6@-36.3,-13.45 U15.6@-37.5,-13.45 U15.7@-35.1,-14 U15.7@-36.3,-14 U15.7@-37.5,-14 U15.8@-35.1,-14.55 U15.8@-36.3,-14.55 U15.8@-37.5,-14.55 U15.9 U17.8 U17.9 U17.10 U17.11@-35.675,-20.67 U17.11@-35.675,-21.7 U17.11@-35.675,-22.73 U23.A3 U23.B2 U23.C2 U25.17@-46.25,-35.5 U27.17@-35.8,-35.7 U28.2 U28.3 U28.4 U28.13 U28.14 U28.17
copper on no net: | length 0
  Top Layer w0.152: -76.52,-1.851 -76.516,-1.847

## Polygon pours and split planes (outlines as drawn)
GND on Bottom Layer "BOTTOM_LAYER_GND_P464" (solid, remove dead copper, pour order 464): -27.4,-20.6 -27,-20.2 -27,-18.405 -27.305,-18.1 -32.692,-18.1 -34.492,-19.9 -34.492,-20.648 -34.344,-20.796 -33.18,-20.796 -32.857,-21.119 -30.669,-21.119 -30.4,-20.85 -29.45,-20.85 -29.2,-20.6
GND on Bottom Layer "BOTTOM_LAYER_GND_P463" (solid, remove dead copper, pour order 463): -20.9,-19.905 -20.805,-20 -20,-20 -19.9,-19.9 -19.9,-16.9 -20,-16.8 -20.827,-16.8 -20.9,-16.873
GND on Bottom Layer "BOTTOM_LAYER_GND_P462" (solid, remove dead copper, pour order 462): 22 vertices, not listed, extent -80.33,-47 7.206,-1.851
HVGND on Bottom Layer "BOTTOM_LAYER_HVGND_P458" (solid, remove dead copper, pour order 458): -22.3,-32.275 -22.3,-33.225 -19.915,-33.225 -18.6,-31.91 -18.6,-29.79 -18.89,-29.5 -19.65,-29.5 -20,-29.85 -20,-31.19 -21.085,-32.275
GND on Bottom Layer "BOTTOM_LAYER_GND_P457" (solid, remove dead copper, pour order 457): -22.9,-32.275 -25.325,-32.275 -25.5,-32.45 -25.5,-34 -25.3,-34.2 -24.15,-34.2 -23.794,-33.844 -23.794,-33.443 -23.576,-33.225 -22.9,-33.225
NetC172_1 on Bottom Layer "BOTTOM_LAYER_NETC172_1_P237" (solid, remove dead copper, pour order 237): 20 vertices, not listed, extent -42.9,-33.7 -20.549,-20.3
HVGND on Bottom Layer "BOTTOM_LAYER_HVGND_P456" (solid, remove dead copper, pour order 456): -8.225,-41.3 -5.3,-41.3 -5,-41.6 -5,-42.05 -5.25,-42.3 -8.225,-42.3 -8.45,-42.075 -8.45,-41.525
GND on Bottom Layer "BOTTOM_LAYER_GND_P455" (solid, remove dead copper, pour order 455): 18 vertices, not listed, extent -18,-6.5 1.704,-3
HVGND on Bottom Layer "BOTTOM_LAYER_HVGND_P454" (solid, remove dead copper, pour order 454): -10.6,-6.7 -10.4,-6.9 -9.375,-6.9 -9.175,-6.7 -7.8,-6.7 -7.65,-6.85 -7.65,-7.6 -7.75,-7.7 -17.85,-7.7 -17.95,-7.6 -17.95,-6.85 -17.8,-6.7
HVGND on Bottom Layer "BOTTOM_LAYER_HVGND_P453" (solid, remove dead copper, pour order 453): -19.3,-17.125 -18.3,-17.125 -18.3,-20.2 -18.4,-20.3 -19.2,-20.3 -19.3,-20.2
NetC15_2 on Bottom Layer "BOTTOM_LAYER_NETC15_2_P452" (solid, remove dead copper, pour order 452): -9.35,-27.95 -9.35,-29.05 -8.25,-30.15 -8.25,-33.5 -6.25,-33.5 -6.25,-31.45 -5.05,-30.25 -5.05,-24.95 -7.05,-24.95 -7.05,-26.15 -8.85,-27.95
NetC1_1 on Bottom Layer "BOTTOM_LAYER_NETC1_1_P451" (solid, remove dead copper, pour order 451): -15.93,-29.55 -15.945,-29.585 -17.315,-29.585 -17.55,-29.35 -17.55,-24.85 -16.297,-23.597 -10.047,-23.597 -9.3,-22.85 -7.7,-22.85 -7.7,-25.65 -8.709,-25.65 -10.05,-26.991 -10.05,-28.3 -15.3,-28.3 -15.93,-28.93
HVGND on Bottom Layer "BOTTOM_LAYER_HVGND_P440" (solid, remove dead copper, pour order 440): -3.675,-6.7 -2.3,-6.7 -2.1,-6.9 -0.791,-6.9 -0.506,-6.614 0.885,-6.614 1.219,-6.948 1.219,-7.672 0.891,-8 -3.7,-8 -3.9,-7.8 -3.9,-6.925
NetC190_1 on Bottom Layer "BOTTOM_LAYER_NETC190_1_P433" (solid, remove dead copper, pour order 433): -26.019,-27.1 -23.75,-27.1 -23.5,-27.35 -23.5,-27.7 -23.4,-27.8 -22.55,-27.8 -22.4,-27.65 -22.4,-25.35 -22.5,-25.25 -25.95,-25.25 -26.169,-25.469 -26.169,-26.95
HVGND on Bottom Layer "BOTTOM_LAYER_HVGND_P421" (solid, remove dead copper, pour order 421): -6.55,-13.1 -7.85,-13.1 -8.25,-13.5 -8.25,-14.935 -8.035,-15.15 -5.05,-15.15 -4.85,-14.95 -1.974,-14.95 -1.75,-14.726 -1.75,-12 -1.95,-11.8 -3.2,-11.8 -3.95,-12.55 -6,-12.55
NetC75_1 on Bottom Layer "BOTTOM_LAYER_NETC75_1_P073" (solid, remove dead copper, pour order 73): -64.675,-33.5 -64.675,-34.5 -64.524,-34.651 -61.551,-34.651 -61.4,-34.5 -59.38,-34.5 -59.38,-34.001 -59.38,-34 -60.3,-34 -60.3,-32.945 -61.645,-32.945 -61.7,-33 -64.175,-33
GND on Bottom Layer "BOTTOM_LAYER_GND_P425" (solid, remove dead copper, pour order 425): 17 vertices, not listed, extent -66.5,-33.3 -59.42,436.818
+5.3V on Bottom Layer "BOTTOM_LAYER_+5.3V_P406" (solid, remove dead copper, pour order 406): 32 vertices, not listed, extent -38.021,-17.5 -16.15,-13.3
NetC125_1 on Bottom Layer "BOTTOM_LAYER_NETC125_1_P089" (solid, remove dead copper, pour order 89): -75.2,-21.4 -75.2,-22.4 -74.3,-22.4 -72.1,-22.4 -72.1,-20.55 -65.9,-20.55 -65.9,-19.385 -67.119,-19.385 -67.119,-20 -75.2,-20
NetC81_1 on Bottom Layer "BOTTOM_LAYER_NETC81_1_P405" (solid, remove dead copper, pour order 405): -54.4,-31.1 -51.6,-31.1 -51.5,-31.2 -51.5,-36 -51.7,-36.2 -54.35,-36.2 -54.5,-36.05 -54.5,-31.2
NetC71_1 on Bottom Layer "BOTTOM_LAYER_NETC71_1_P404" (solid, remove dead copper, pour order 404): 19 vertices, not listed, extent -58.5,-36.25 -55.35,-31.1
GND on Bottom Layer "BOTTOM_LAYER_GND_P400" (solid, remove dead copper, pour order 400): -70.3,-26.1 -70.1,-26.3 -68.6,-26.3 -68.5,-26.2 -68.5,-24.95 -68.65,-24.8 -70.1,-24.8 -70.3,-25
MHV on Bottom Layer "BOTTOM_LAYER_MHV_P278" (solid, remove dead copper, pour order 278): -13.725,-38.5 -13.725,-37.5 -16.275,-37.5 -16.275,-38.5
NetC56_1 on Bottom Layer "BOTTOM_LAYER_NETC56_1_P386" (solid, remove dead copper, pour order 386): 20 vertices, not listed, extent -53.9,-18.075 -49.95,-10.65
VDD on Bottom Layer "BOTTOM_LAYER_VDD_P371" (solid, remove dead copper, pour order 371): -66.7,-35.425 -66.7,-36.375 -66.725,-36.4 -69.1,-36.4 -69.1,-34.6 -68.3,-34.6 -68.3,-35.2 -67.925,-35.2 -67.7,-35.425
NetC3_1 on Bottom Layer "BOTTOM_LAYER_NETC3_1_P370" (solid, remove dead copper, pour order 370): -17.502,-19.7 -17.502,-22.1 -10.098,-22.1 -10.098,-19.796 -10.05,-19.748 -10.098,-19.7 -12.078,-19.7 -12.281,-19.497 -12.281,-15.056 -12,-14.775 -12,-13.825 -15.425,-13.825 -15.65,-14.05 -15.65,-19.429 -15.921,-19.7
NetC174_1 on Bottom Layer "BOTTOM_LAYER_NETC174_1_P368" (solid, remove dead copper, pour order 368): 20 vertices, not listed, extent -50.25,-38.1 -46.88,-35.63
VBUS on Bottom Layer "BOTTOM_LAYER_VBUS_P366" (solid, remove dead copper, pour order 366): 19 vertices, not listed, extent -59.95,-25.8 -57.75,-17.2
NetC10_1 on Bottom Layer "BOTTOM_LAYER_NETC10_1_P364" (solid, remove dead copper, pour order 364): 17 vertices, not listed, extent -5.9,-13.8 0.7,-10.45
NetC6_1 on Bottom Layer "BOTTOM_LAYER_NETC6_1_P362" (solid, remove dead copper, pour order 362): 1.2,-12 1.6,-12.4 1.6,-13.55 1.85,-13.8 2.925,-13.8 3.15,-13.575 3.15,-10.85 2.9,-10.6 1.4,-10.6 1.2,-10.8
GND on Bottom Layer "BOTTOM_LAYER_GND_P359" (solid, remove dead copper, pour order 359): -75.5,-22.6 -64.2,-22.6 -63.925,-22.875 -63.925,-24 -64.125,-24.2 -75.45,-24.2 -75.75,-23.9 -75.75,-22.85
GND on Bottom Layer "BOTTOM_LAYER_GND_P358" (solid, remove dead copper, pour order 358): -73.7,-10.75 -74.05,-11.1 -74.05,-12.4 -73.75,-12.7 -63.881,-12.7 -63.85,-12.669 -63.85,-12.7 -58.5,-12.7 -58.09,-12.289 -58.09,-11.511 -58.3,-11.3 -61.249,-11.3 -61.799,-10.75 -72.7,-10.75
GND on Bottom Layer "BOTTOM_LAYER_GND_P357" (solid, remove dead copper, pour order 357): -32.75,-34.7 -32.318,-34.268 -28.286,-34.268 -28.05,-34.504 -28.05,-35.302 -28.448,-35.7 -32.625,-35.7 -33.6,-35.7 -33.8,-35.5 -33.8,-34.8 -33.7,-34.7
GND on Bottom Layer "BOTTOM_LAYER_GND_P355" (solid, remove dead copper, pour order 355): 28 vertices, not listed, extent -25.5,-38.017 -21.55,-34.55
GND on Bottom Layer "BOTTOM_LAYER_GND_P348" (solid, remove dead copper, pour order 348): 17 vertices, not listed, extent -62.9,-26.4 -60.2,-23.7
NetC58_1 on Bottom Layer "BOTTOM_LAYER_NETC58_1_P345" (solid, remove dead copper, pour order 345): -54.9,-16.3 -55,-16.4 -55.7,-16.4 -56.3,-17 -58.8,-17 -59,-16.8 -59,-14.8 -58.9,-14.7 -55.9,-14.7 -55.8,-14.8 -55.8,-15.6 -55.7,-15.7 -55,-15.7 -54.9,-15.8
GND on Bottom Layer "BOTTOM_LAYER_GND_P052" (solid, remove dead copper, pour order 52): 20 vertices, not listed, extent -37.95,-13.625 -27.7,-11.2
GND on Bottom Layer "BOTTOM_LAYER_GND_P338" (solid, remove dead copper, pour order 338): 20 vertices, not listed, extent -78.5,-40.5 5.5,-8.5
NetC1_2 on Bottom Layer "BOTTOM_LAYER_NETC1_2_P301" (solid, remove dead copper, pour order 301): -9.6,-20.5 -9,-21.1 -1.7,-21.1 -1.6,-21 -1.6,-18.5 -1.935,-18.165 -5.985,-18.165 -6.25,-17.9 -6.25,-15.9 -9.1,-15.9 -9.6,-16.4
NetC22_2 on Bottom Layer "BOTTOM_LAYER_NETC22_2_P205" (solid, remove dead copper, pour order 205): -4.9,-34.25 -4.9,-35.35 -1,-35.35 -1,-35.003 0.247,-35.003 0.25,-35 0.25,-33.2 -0.55,-33.2 -0.55,-34.25 -1,-34.25
HVGND on Bottom Layer "BOTTOM_LAYER_HVGND_P295" (solid, remove dead copper, pour order 295): -8,-37.481 -8,-38.751 3.749,-38.751 3.9,-38.6 3.9,-14.6 3.7,-14.4 1.975,-14.4 1.8,-14.575 1.8,-31.8 2.1,-32.1 2.1,-37.2 2,-37.3 -7.819,-37.3
HVGND on Bottom Layer "BOTTOM_LAYER_HVGND_P294" (solid, remove dead copper, pour order 294): -6.9,-22 -6.9,-24.3 -6.6,-24.6 -1.9,-24.6 -1.6,-24.3 -1.6,-22
HVGND on Bottom Layer "BOTTOM_LAYER_HVGND_P116" (solid, remove dead copper, pour order 116): 17 vertices, not listed, extent -16.1,-31.875 -10,-28.5
HVGND on Bottom Layer "BOTTOM_LAYER_HVGND_P293" (solid, remove dead copper, pour order 293): -19.3,-35.5 -18.5,-35.5 -18.5,-35.1 -18.1,-34.7 -18.1,-33.9 -18.5,-33.5 -19.092,-33.5 -19.3,-33.708
PHV on Bottom Layer "BOTTOM_LAYER_PHV_P270" (solid, remove dead copper, pour order 270): -12.175,-10.3 -12.075,-10.4 -12.075,-11.2 -12.175,-11.3 -14.9,-11.3 -15,-11.4 -15,-11.8 -15.1,-11.9 -16.2,-11.9 -16.3,-11.8 -16.3,-10.7 -16.3,-10.4 -16.2,-10.3
NetC112_1 on Bottom Layer "BOTTOM_LAYER_NETC112_1_P260" (solid, remove dead copper, pour order 260): -26.8,-16.525 -25.744,-16.525 -21.9,-16.525 -21.9,-18 -26.8,-18
VBUS on Bottom Layer "BOTTOM_LAYER_VBUS_P228" (solid, remove dead copper, pour order 228): -21.516,-10.599 -21.518,-10.6 -26.8,-10.6 -26.8,-13 -24.3,-13 -24.3,-11.619 -21.516,-11.619
NetC18_2 on Bottom Layer "BOTTOM_LAYER_NETC18_2_P206" (solid, remove dead copper, pour order 206): 0.925,-36.1 0.925,-37.1 1.875,-37.1 1.875,-35.025 1.85,-35 1.85,-32.4 0.5,-32.4 0.5,-31.3 -0.85,-31.3 -1,-31.45 -1,-32.9 0.925,-32.9 0.925,-33.6
NetC79_1 on Bottom Layer "BOTTOM_LAYER_NETC79_1_P202" (solid, remove dead copper, pour order 202): -45.55,-21.65 -43.35,-21.65 -43.35,-27.95 -45.55,-27.95
GND on Bottom Layer "BOTTOM_LAYER_GND_P074" (solid, remove dead copper, pour order 74): -70.4,-33.3 -70.4,-36.4 -69.5,-36.4 -69.5,-35.8 -69.5,-33.9 -69.5,-33.3
NetC122_2 on Bottom Layer "BOTTOM_LAYER_NETC122_2_P198" (solid, remove dead copper, pour order 198): -36.075,-19.9 -36.075,-22.743 -36.089,-22.729 -37.7,-22.729 -37.7,-23.825 -37.7,-24.775 -37.475,-25 -34.6,-25 -34.6,-19.9
GND on Bottom Layer "BOTTOM_LAYER_GND_P196" (solid, remove dead copper, pour order 196): -40.519,-17.1 -37.381,-17.1 -37.381,-18.7 -38.313,-18.7 -38.313,-20.906 -38.3,-20.919 -42.1,-20.919 -42.1,-19.649 -40.5,-19.649 -40.5,-17.119
GND on Bottom Layer "BOTTOM_LAYER_GND_P094" (solid, remove dead copper, pour order 94): -74.3,-19.8 -73.3,-19.8 -73.3,-16.3 -74.3,-16.3 -74.3,-17.6 -76.94,-17.6 -76.94,-19.4 -74.3,-19.4
NetC109_1 on Bottom Layer "BOTTOM_LAYER_NETC109_1_P182" (solid, remove dead copper, pour order 182): -25.5,-14.7 -21.4,-14.7 -21.4,-15.9 -25.5,-15.9
NetC195_1 on Bottom Layer "BOTTOM_LAYER_NETC195_1_P176" (solid, remove dead copper, pour order 176): -28.201,-25.65 -28.051,-25.5 -26.781,-25.5 -26.781,-27.1 -28.051,-27.1 -28.051,-27.006 -28.11,-26.947 -29.9,-26.947 -29.9,-27.6 -40.6,-27.6 -40.6,-25.65
NetC172_1 on Bottom Layer "BOTTOM_LAYER_NETC172_1_P175" (solid, remove dead copper, pour order 175): -40.15,-33.85 -39.45,-34.55 -39.45,-37.05 -40.2,-37.8 -41.7,-37.8 -41.7,-33.85
GND on Bottom Layer "BOTTOM_LAYER_GND_P037" (solid, remove dead copper, pour order 37): 17 vertices, not listed, extent -37.7,-38.41 -35.4,-35.4
VDD_CLK_2.5V on Bottom Layer "BOTTOM_LAYER_VDD_CLK_2.5V_P169" (solid, remove dead copper, pour order 169): -68.089,-25.4 -67.089,-25.4 -67.089,-27.625 -68.089,-27.625 -68.089,-26.625
NetC189_1 on Bottom Layer "BOTTOM_LAYER_NETC189_1_P161" (solid, remove dead copper, pour order 161): -39,-32 -39,-33.2 -36.1,-33.2 -36.1,-34.55 -36.05,-34.6 -36.035,-34.585 -34.945,-34.585 -34.945,-32.845 -34.2,-32.1 -32.325,-32.1 -32.325,-31.1 -34.9,-31.1 -35.8,-32
NetC120_1 on Bottom Layer "BOTTOM_LAYER_NETC120_1_P134" (solid, remove dead copper, pour order 134): -38.1,-19.19 -36.7,-19.19 -36.7,-19.61 -36.71,-19.6 -37.8,-19.6 -37.8,-21.9 -38.2,-21.9 -38.2,-22.9 -38.3,-23 -39.851,-23 -39.9,-22.951 -39.9,-21.5 -38.1,-21.5
NetC120_1 on Bottom Layer "BOTTOM_LAYER_NETC120_1_P128" (solid, remove dead copper, pour order 128): -42.1,-23 -38.3,-23 -38.2,-22.9 -38.2,-21.9 -36.7,-21.9 -36.7,-21.5 -42,-21.5 -42.1,-21.6
HVGND on Bottom Layer "BOTTOM_LAYER_HVGND_P104" (solid, remove dead copper, pour order 104): -11.519,-19.2 -10.249,-19.2 -10.249,-13.976 -10.4,-13.825 -11.4,-13.825 -11.4,-15.281 -11.519,-15.4
GND on Bottom Layer "BOTTOM_LAYER_GND_P004" (solid, remove dead copper, pour order 4): -56.5,-26.095 -52.345,-26.095 -52.195,-26.245 -52.195,-25.395 -52.877,-25.523 -52.825,-25.575 -52.825,-24 -56.5,-24
NetC171_1 on Bottom Layer "BOTTOM_LAYER_NETC171_1_P096" (solid, remove dead copper, pour order 96): -44.82,-35.1 -42.41,-35.1 -42.35,-35.16 -42.35,-36.358 -45.087,-36.358 -45.1,-36.37 -45.135,-36.334 -45.135,-35.145 -44.865,-35.145
NetC147_2 on Bottom Layer "BOTTOM_LAYER_NETC147_2_P079" (solid, remove dead copper, pour order 79): -66.2,-17.785 -65.05,-17.785 -65.05,-17.5 -65.05,-16.3 -64.85,-16.1 -60.35,-16.1 -60.15,-16.3 -60.2,-16.35 -60.2,-18.015 -66.2,-18.015
NetC134_2 on Bottom Layer "BOTTOM_LAYER_NETC134_2_P080" (solid, remove dead copper, pour order 80): -66,-18.585 -65.985,-18.6 -60.2,-18.6 -60.2,-19.9 -60.4,-20.1 -60.5,-20 -64.8,-20 -65,-19.8 -65,-18.85 -65.965,-18.85 -66,-18.815
NetC145_1 on Bottom Layer "BOTTOM_LAYER_NETC145_1_P082" (solid, remove dead copper, pour order 82): -73.947,-13.17 -73.947,-14.8 -71.747,-14.8 -71.747,-15.253 -70.7,-16.3 -67.7,-16.3 -67.7,-17.163 -67.648,-17.215 -65.952,-17.215 -65.919,-17.181 -65.919,-15.5 -70.1,-15.5 -70.1,-13.17
NetC145_1 on Bottom Layer "BOTTOM_LAYER_NETC145_1_P093" (solid, remove dead copper, pour order 93): -76.57,-13.17 -77,-13.6 -77,-16.212 -76.677,-16.535 -75.712,-16.535 -75.5,-16.323 -75.5,-15.668 -75.525,-15.693 -73.5,-15.693 -73.5,-15.3 -73.5,-14.44 -72.347,-14.44 -72.347,-13.17
NetC127_1 on Bottom Layer "BOTTOM_LAYER_NETC127_1_P085" (solid, remove dead copper, pour order 85): -71.5,-22 -63.9,-22 -63.9,-21.4 -65.25,-21.4 -65.25,-19.15 -65.4,-19 -66.4,-19 -66.4,-19.2 -65.7,-19.2 -65.7,-20.749 -71.5,-20.749
NetC135_1 on Bottom Layer "BOTTOM_LAYER_NETC135_1_P083" (solid, remove dead copper, pour order 83): 20 vertices, not listed, extent -69.6,-17.615 -59.925,-13
NetC72_1 on Bottom Layer "BOTTOM_LAYER_NETC72_1_P072" (solid, remove dead copper, pour order 72): -57.2,-26.7 -57.181,-26.681 -54.081,-26.681 -54.081,-26.4 -53.37,-26.38 -53.3,-26.45 -53.3,-27.4 -53.285,-27.385 -52.365,-27.385 -52.365,-27.915 -52.401,-27.951 -56,-27.951 -56,-27.515 -57.185,-27.515 -57.2,-27.5
GND on Bottom Layer "BOTTOM_LAYER_GND_P066" (solid, remove dead copper, pour order 66): -57.306,-17.43 -57.306,-19 -57.519,-19 -57.519,-22.8 -54.1,-22.8 -54.1,-21 -56.1,-21 -56.1,-17.4 -57.275,-17.4
GND on Bottom Layer "BOTTOM_LAYER_GND_P057" (solid, remove dead copper, pour order 57): 19 vertices, not listed, extent -59.6,-15.425 -53.925,-11.5
NetC94_1 on Bottom Layer "BOTTOM_LAYER_NETC94_1_P055" (solid, remove dead copper, pour order 55): -34.65,-13.825 -39.375,-13.825 -39.4,-13.8 -39.4,-10.45 -43.216,-10.45 -43.483,-10.717 -43.483,-12.606 -40.3,-12.606 -40.3,-14.8 -38.4,-14.8 -38.4,-14.193 -38.382,-14.175 -34.65,-14.175
NetC95_1 on Bottom Layer "BOTTOM_LAYER_NETC95_1_P054" (solid, remove dead copper, pour order 54): -43.497,-14.827 -40.703,-14.827 -40.703,-16.683 -41.281,-17.1 -41.281,-18.7 -42.551,-18.7 -42.551,-17.1 -43.5,-17.1 -43.497,-17.097
GND on Bottom Layer "BOTTOM_LAYER_GND_P050" (solid, remove dead copper, pour order 50): -33.7,-28.081 -29.9,-28.081 -29.813,-27.994 -29.3,-27.994 -29.3,-27.4 -23.9,-27.4 -23.9,-29.4 -33.7,-29.4
GND on Bottom Layer "BOTTOM_LAYER_GND_P047" (solid, remove dead copper, pour order 47): 17 vertices, not listed, extent -50,-36.325 -45.425,-33.849
NetC192_1 on Bottom Layer "BOTTOM_LAYER_NETC192_1_P039" (solid, remove dead copper, pour order 39): 26 vertices, not listed, extent -35.62,-38.41 -27,-36.3
NetC18_2 on Bottom Layer "BOTTOM_LAYER_NETC18_2_P007" (solid, remove dead copper, pour order 7): -2,-25 0.5,-25 0.5,-32.9 -2.1,-32.9 -2.1,-30.25 -2.1,-25.1
NetC6_1 on Bottom Layer "BOTTOM_LAYER_NETC6_1_P006" (solid, remove dead copper, pour order 6): -4.067,-15.9 0.6,-15.9 0.7,-16 0.7,-24 0.5,-24.2 -1,-24.2 -1,-18 -1.1,-17.9 -4.035,-17.9 -4.035,-15.921 -4.056,-15.9
NetC70_1 on Bottom Layer "BOTTOM_LAYER_NETC70_1_P002" (solid, remove dead copper, pour order 2): -51.065,-25.915 -51.05,-25.9 -48.7,-25.9 -48.7,-29.5 -51.025,-29.5 -51.065,-29.46
GND on Top Layer "TOP_LAYER_GND_P461" (solid, remove dead copper, pour order 461): -30.134,-1.774 -29.908,-2 6,-2 7.13,-3.13 7.13,-44.87 5,-47 4.943,-46.943 -79.057,-46.943 -80,-46 -80,-2 -30.283,-2 -30.134,-1.851
GND on Top Layer "TOP_LAYER_GND_P432" (solid, remove dead copper, pour order 432): -10.95,-14.55 -10.75,-14.35 -9.55,-14.35 -9.35,-14.55 -9.35,-17.75 -9.15,-17.95 -8.35,-17.95 -8.35,-18.75 -8.6,-19 -9.4,-19 -9.55,-18.85 -9.9,-18.85 -10.1,-18.65 -10.1,-16.1 -10.95,-15.25
NetC190_1 on Top Layer "TOP_LAYER_NETC190_1_P373" (solid, remove dead copper, pour order 373): 24 vertices, not listed, extent -19.9,-34.1 4.15,-14.9
GND on Top Layer "TOP_LAYER_GND_P342" (solid, remove dead copper, pour order 342): -2,-33.9 -1.6,-33.9 -1.6,-33 -1.5,-32.9 -0.1,-32.9 0,-33 0,-34.3 0.2,-34.5 0.8,-34.5 0.95,-34.35 0.95,-32.7 0.45,-32.2 -1.7,-32.2 -2.6,-33.1 -2.6,-33.9
1V8_DVDD on Top Layer "TOP_LAYER_1V8_DVDD_P392" (solid, remove dead copper, pour order 392): 31 vertices, not listed, extent -15.575,-14.5 -9.3,-4.038
AVDD_1P2 on Top Layer "TOP_LAYER_AVDD_1P2_P417" (solid, remove dead copper, pour order 417): 25 vertices, not listed, extent -12.7,-14.35 -5.8,-4.038
USB_5V on Top Layer "TOP_LAYER_USB_5V_P416" (solid, remove dead copper, pour order 416): 19 vertices, not listed, extent -7.1,-15 -3.5,-4.05
NetC192_1 on Top Layer "TOP_LAYER_NETC192_1_P407" (solid, remove dead copper, pour order 407): -33.8,-32 -35,-32 -35.3,-32.3 -35.3,-36.85 -34.9,-37.25 -32.2,-37.25 -32,-37.05 -32,-36.5 -32.5,-36 -32.5,-35 -33.4,-34.1 -33.4,-32.4
GND on Top Layer "TOP_LAYER_GND_P399" (solid, remove dead copper, pour order 399): -70.1,-26.3 -70.3,-26.1 -70.3,-25 -70.1,-24.8 -68.65,-24.8 -68.5,-24.95 -68.5,-26.2 -68.6,-26.3
VCCO_2V5 on Top Layer "TOP_LAYER_VCCO_2V5_P398" (solid, remove dead copper, pour order 398): 22 vertices, not listed, extent -9.65,-41.65 -4.825,-32.85
NetC63_1 on Top Layer "TOP_LAYER_NETC63_1_P397" (solid, remove dead copper, pour order 397): -6.325,-32.5 -6.525,-32.7 -7.9,-32.7 -8.3,-32.3 -8.3,-28.7 -7.9,-28.3 -3.85,-28.3 -3.55,-28.6 -3.55,-30 -3.75,-30.2 -6.1,-30.2 -6.325,-30.425 -6.325,-31.5
1V8_DVDD on Top Layer "TOP_LAYER_1V8_DVDD_P395" (solid, remove dead copper, pour order 395): -10.2,-32.2 -9.15,-32.2 -8.95,-32.4 -8.95,-33.9 -9.15,-34.1 -10.25,-34.1 -10.4,-33.95 -10.4,-32.4
GND on Top Layer "TOP_LAYER_GND_P393" (solid, remove dead copper, pour order 393): -11.825,-30.9 -8.65,-30.9 -8.5,-31.05 -8.5,-31.75 -8.65,-31.9 -11.825,-31.9
GND on Top Layer "TOP_LAYER_GND_P391" (solid, remove dead copper, pour order 391): 17 vertices, not listed, extent -22.075,-31.1 -18.325,-28.4
1V8_DVDD on Top Layer "TOP_LAYER_1V8_DVDD_P390" (solid, remove dead copper, pour order 390): -9.046,-44.614 -8.996,-44.664 -8.325,-44.664 -8.3,-44.639 -8.3,-41.8 -8.45,-41.65 -8.941,-41.65 -9.046,-41.754 -9.046,-42.714
1V8_DVDD on Top Layer "TOP_LAYER_1V8_DVDD_P388" (solid, remove dead copper, pour order 388): -14.1,-41.8 -13.9,-42 -13.45,-42 -13.296,-41.846 -13.296,-35.954 -13.55,-35.7 -14.475,-35.7 -14.7,-35.925 -14.7,-36.627 -14.452,-36.875 -14.275,-36.875 -14.1,-37.05
GND on Top Layer "TOP_LAYER_GND_P374" (solid, remove dead copper, pour order 374): -31.65,-34.25 -31.95,-34.55 -31.95,-36.1 -31.4,-36.65 -26.9,-36.65 -26.85,-36.6 -26.85,-34.475 -27.075,-34.25
VBUS on Top Layer "TOP_LAYER_VBUS_P367" (solid, remove dead copper, pour order 367): -29.95,-33.05 -31.581,-33.05 -31.749,-32.882 -31.749,-32.3 -31.949,-32.1 -32.819,-32.1 -33.019,-32.3 -33.019,-33.9 -32.919,-34 -29.7,-34 -29.7,-33.3
NetC79_1 on Top Layer "TOP_LAYER_NETC79_1_P361" (solid, remove dead copper, pour order 361): -3.45,-30.4 -3.05,-30.8 -3.05,-33.925 -3.225,-34.1 -4.25,-34.1 -4.55,-33.8 -4.55,-31.45 -4.7,-31.3 -5.95,-31.3 -6.1,-31.15 -6.1,-30.55 -5.95,-30.4
1V2_DVDD on Top Layer "TOP_LAYER_1V2_DVDD_P360" (solid, remove dead copper, pour order 360): 23 vertices, not listed, extent -2.046,-44.664 4.35,-34.1
GND on Top Layer "TOP_LAYER_GND_P356" (solid, remove dead copper, pour order 356): -29.1,-28 -28.9,-28.2 -28.9,-29.123 -29.077,-29.3 -31.5,-29.3 -31.6,-29.2 -31.6,-28.2 -31.4,-28
GND on Top Layer "TOP_LAYER_GND_P107" (solid, remove dead copper, pour order 107): -39.4,-35.9 -38.6,-35.9 -38.6,-36.7 -40.3,-36.7 -40.3,-33.2 -39.4,-33.2
NetC79_1 on Top Layer "TOP_LAYER_NETC79_1_P346" (solid, remove dead copper, pour order 346): -43.7,-29.3 -43.35,-28.95 -43.35,-23.95 -43.5,-23.8 -45.4,-23.8 -45.55,-23.95 -45.55,-29.025 -45.275,-29.3
NetC58_1 on Top Layer "TOP_LAYER_NETC58_1_P344" (solid, remove dead copper, pour order 344): -58.9,-16.683 -58.9,-15 -58.7,-14.8 -55.9,-14.8 -55.795,-14.905 -55.795,-15.43 -55.5,-15.725 -55.5,-16.9 -55.3,-17.1 -55.3,-18.867 -55.333,-18.9 -56.603,-18.9 -56.603,-17.097 -56.7,-17 -58.629,-17
NetC125_1 on Top Layer "TOP_LAYER_NONET_P343" (solid, remove dead copper, pour order 343): -4.165,-15.665 -4,-15.5 -4,-13.895 -4.33,-13.565 -5.35,-13.565 -5.59,-13.805 -5.59,-15.435 -5.36,-15.665
GND on Top Layer "TOP_LAYER_GND_P340" (solid, remove dead copper, pour order 340): 5.5,-40.5 4.5,-40.5 4.5,-9.5 5.5,-9.5
GND on Top Layer "TOP_LAYER_GND_P339" (solid, remove dead copper, pour order 339): -18.5,-39.5 -18.5,-40.5 -78,-40.5 -78.5,-40 -78.5,-9 -78,-8.5 -17.5,-8.5 -17.5,-9.5 -77,-9.5 -77.5,-10 -77.5,-39 -77,-39.5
